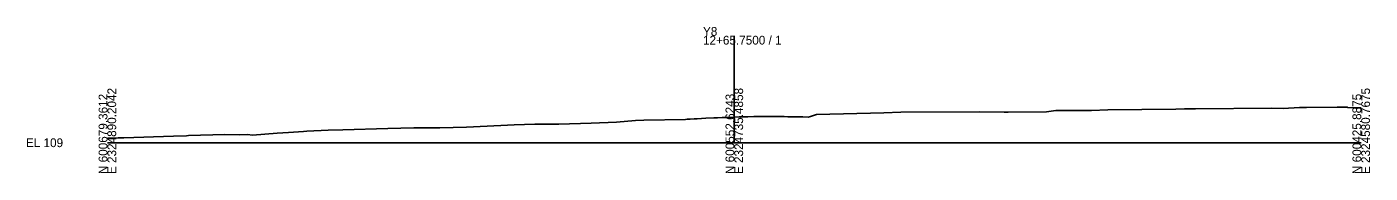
# Model space of a CAD drawing. Extents: x -26 to 2324730, y 979 to 600638.
# Drawn here: x 2774.3 to 3202.8, y 990.3 to 1037 of the extents above; entities that cross this region are included whole.
import ezdxf

# ---------------------------------------------------------------- set-up
doc = ezdxf.new("R2010")
doc.units = 0
for name, color, linetype in [('Exist CMT Pavement', 7, 'Continuous'), ('Exist Cross Section Cell', 7, 'Continuous'), ('Exist XS Center Line Elevation Label', 7, 'Continuous'), ('Exist XS Ground Line', 7, 'Continuous'), ('Prop XS Earthwork Shape', 7, 'Continuous')]:
    doc.layers.add(name, color=color, linetype=linetype)

msp = doc.modelspace()

# ---------------------------------------------------------------- linework, layer by layer
at = {"layer": 'Exist CMT Pavement'}
for p, q in [((3000, 1008.15), (3000, 1008.25)), ((3000, 1008.25), (3000.1, 1008.25)), ((3000.1, 1008.25), (3000.1, 1008.15))]:
    msp.add_line(p, q, dxfattribs=at)
at = {"layer": 'Exist Cross Section Cell'}
for p, q in [((3000, 1000), (3000, 1034.11)), ((2800, 1000), (3000, 1000)), ((3000, 1000), (3200, 1000))]:
    msp.add_line(p, q, dxfattribs=at)
at = {"layer": 'Exist XS Ground Line'}
msp.add_lwpolyline([(2800, 1001.41), (2803.47, 1001.53), (2805.24, 1001.59), (2821.08, 1002.06), (2825.26, 1002.24), (2825.84, 1002.33), (2837.5, 1002.66), (2842.05, 1002.56), (2844.74, 1002.6), (2846.29, 1002.46), (2854.13, 1003.05), (2855.96, 1003.2), (2857.73, 1003.3), (2862.54, 1003.6), (2863.66, 1003.68), (2870.47, 1004.05), (2875.08, 1004.07), (2889.47, 1004.59), (2897.77, 1004.78), (2906.03, 1004.77), (2914.61, 1005), (2925.55, 1005.48), (2929.79, 1005.67), (2936.38, 1005.91), (2943.98, 1005.96), (2954.35, 1006.28), (2962.45, 1006.57), (2968.48, 1007.05), (2971.12, 1007.23), (2984.47, 1007.44), (2985, 1007.5), (2985.9, 1007.51), (2987.14, 1007.6), (2988.1, 1007.66), (2990.88, 1007.83), (2993.47, 1007.92), (2994.6, 1007.95), (2996.15, 1008), (2997.49, 1008.05), (2998.84, 1008.09), (2999.7, 1008.13), (3000, 1008.15), (3001.52, 1008.21), (3004.36, 1008.3), (3006.18, 1008.36), (3006.89, 1008.37), (3008.51, 1008.39), (3009.57, 1008.4), (3011.23, 1008.4), (3012.52, 1008.38), (3014.2, 1008.35), (3015.87, 1008.32), (3017.02, 1008.3), (3017.88, 1008.29), (3018.53, 1008.28), (3019.06, 1008.27), (3019.48, 1008.26), (3019.84, 1008.26), (3021.14, 1008.24), (3021.83, 1008.25), (3023.61, 1008.16), (3024.33, 1008.37), (3026.25, 1008.97), (3047.71, 1009.56), (3053.15, 1009.75), (3078.17, 1009.84), (3086.11, 1009.8), (3086.51, 1009.8), (3087.35, 1009.8), (3099.55, 1009.9), (3102.58, 1010.25), (3105.76, 1010.27), (3106.7, 1010.26), (3109.08, 1010.29), (3110.12, 1010.26), (3113.05, 1010.29), (3113.92, 1010.3), (3119.16, 1010.54), (3140.86, 1010.74), (3143.61, 1010.78), (3147.09, 1010.83), (3171.47, 1011), (3175.14, 1010.96), (3180.27, 1011.19), (3180.69, 1011.27), (3181.51, 1011.29), (3182.57, 1011.29), (3192.29, 1011.34), (3195.57, 1011.37), (3195.72, 1011.2), (3197.34, 1011.11), (3200, 1011.13)], dxfattribs=at)
at = {"layer": 'Prop XS Earthwork Shape'}
msp.add_lwpolyline([(3000, 1008.15), (3000, 1008.25), (3000.1, 1008.25), (3000.1, 1008.15)], close=True, dxfattribs=at)

# ---------------------------------------------------------------- texts
at = {"layer": 'Exist Cross Section Cell'}
for s, p in [('Y8', (2990, 1034.11)), ('12+65.7500 / 1', (2990, 1031.31)), ('EL 109', (2774, 998.6))]:
    msp.add_text(s, height=2.8, dxfattribs=at).set_placement(p)
for s, p in [('E 2324890.2042', (2802.8, 990)), ('E 2324735.4858', (3002.8, 990)), ('E 2324580.7675', (3202.8, 990)), ('N 600679.3612', (2800, 990)), ('N 600552.6243', (3000, 990)), ('N 600425.8875', (3200, 990))]:
    msp.add_text(s, height=2.8, rotation=90, dxfattribs=at).set_placement(p)
at = {"layer": 'Exist XS Center Line Elevation Label'}
msp.add_text('117.15', height=0.2, dxfattribs=at).set_placement((2999.71, 1006.15))

doc.saveas('drawing.dxf')
